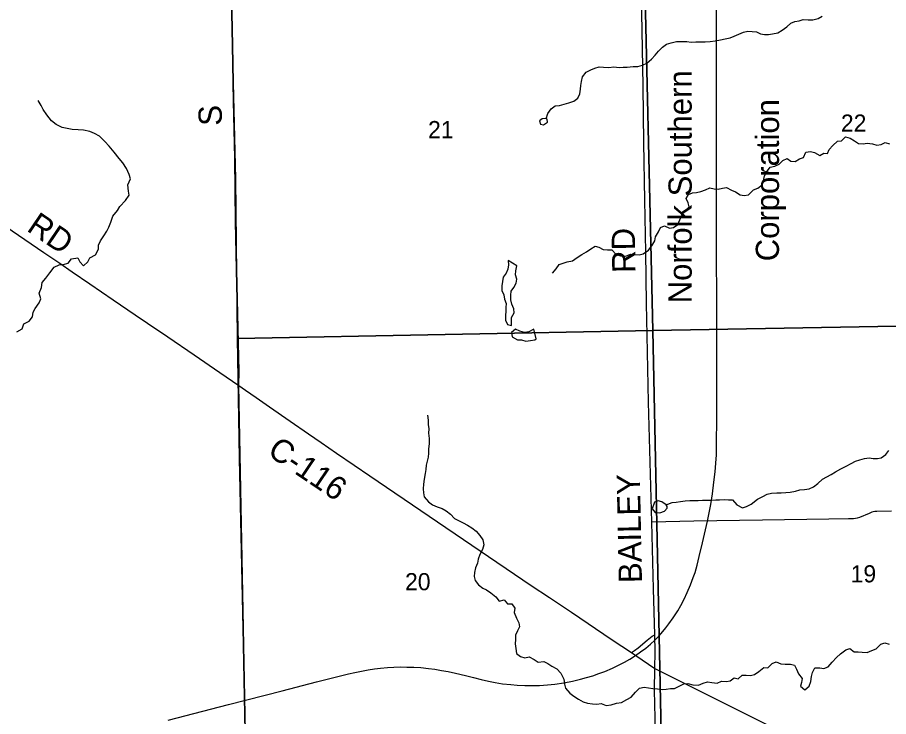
# Model space of a CAD drawing. Extents: x 0 to 34, y 0 to 22.
# Drawn here: x 6.707 to 8.833, y 18.248 to 19.953 of the extents above; entities that cross this region are included whole.
import ezdxf

# ---------------------------------------------------------------- set-up
doc = ezdxf.new("R2010")
doc.units = 0
for name, color, linetype in [('GM_X_Corporation', 7, 'Continuous'), ('GM_X_County_Road', 7, 'Continuous'), ('GM_X_County_Road_Text', 7, 'Continuous'), ('GM_X_Minor_Lake', 7, 'Continuous'), ('GM_X_Minor_River', 7, 'Continuous'), ('GM_X_Rail_Line', 7, 'Continuous'), ('GM_X_Rail_Line_Text', 7, 'Continuous'), ('GM_X_Section_Text', 7, 'Continuous')]:
    doc.layers.add(name, color=color, linetype=linetype)

msp = doc.modelspace()

# ---------------------------------------------------------------- linework, layer by layer
at = {"layer": 'GM_X_Corporation'}
for points in [[(9.7895, 15.1275), (9.7895, 20.2375), (9.7789, 20.2374), (8.9707, 20.221), (8.4324, 20.2139), (8.2231, 20.2112), (7.2254, 20.198), (7.2266, 20.122), (7.2291, 20.0061), (7.2317, 19.8848), (7.2344, 19.7492), (7.237, 19.6097), (7.2392, 19.4543), (7.2426, 19.2998), (7.2468, 19.0896), (7.2467, 19.0557), (7.2751, 17.5764), (7.2764, 17.5202), (7.2799, 17.4174), (7.283, 17.3071), (7.2872, 17.1772)], [(7.2872, 17.1772), (7.283, 17.3071), (7.2799, 17.4174), (7.2764, 17.5202), (7.2751, 17.5764), (7.2467, 19.0557), (7.2468, 19.0896), (7.2426, 19.2998), (7.2392, 19.4543), (7.237, 19.6097), (7.2344, 19.7492), (7.2317, 19.8848), (7.2291, 20.0061), (7.2266, 20.122), (7.2254, 20.198), (6.0786, 20.1754), (5.7004, 20.168), (4.9925, 20.1548), (3.1549, 20.1187), (2.9895, 20.1176), (2.9895, 14.989)]]:
    msp.add_lwpolyline(points, dxfattribs=at)
for points in [[(9.2406, 20.2272), (9.2644, 19.2076), (8.2571, 19.1893), (8.2335, 20.2135), (8.7368, 20.2215)], [(8.2335, 20.2135), (8.2571, 19.1893), (7.2437, 19.1696), (7.2401, 19.5595), (7.2243, 20.1958), (7.7364, 20.2052)], [(8.2571, 19.1893), (9.2644, 19.2076), (9.2853, 18.1891), (8.2786, 18.1687)], [(7.2437, 19.1696), (8.2571, 19.1893), (8.2786, 18.1687), (7.2643, 18.1469), (7.2627, 18.2368), (7.2488, 18.8774)]]:
    msp.add_lwpolyline(points, close=True, dxfattribs=at)
at = {"layer": 'GM_X_County_Road'}
for points in [[(8.2622, 18.3652), (8.2632, 18.4054), (8.2621, 18.4472), (8.2592, 18.5595), (8.2549, 18.7216), (8.2466, 19.0147), (8.2435, 19.1769), (8.2421, 19.255), (8.2402, 19.3805), (8.2379, 19.507), (8.2357, 19.6472), (8.2338, 19.785), (8.2321, 19.8769), (8.2296, 20.0073), (8.2268, 20.1925), (8.2264, 20.1978), (8.2261, 20.2017), (8.2255, 20.2048), (8.2246, 20.2076), (8.2233, 20.2106), (8.2177, 20.2203)], [(7.2469, 19.0552), (7.247, 19.089), (7.2428, 19.2992), (7.2394, 19.4537), (7.2372, 19.6092), (7.2346, 19.7487), (7.2319, 19.8843), (7.2293, 20.0056), (7.2268, 20.1215), (7.2256, 20.1974)], [(6.0866, 19.9058), (6.1443, 19.8572), (6.2021, 19.8083), (6.2352, 19.7801), (6.2988, 19.727), (6.3765, 19.6635), (6.4512, 19.6033), (6.4897, 19.573), (6.5179, 19.5524), (6.5426, 19.5352), (6.5762, 19.5126), (6.6344, 19.4729), (6.6938, 19.4327), (6.7714, 19.3798), (6.8099, 19.3535), (6.8403, 19.3326), (6.8836, 19.3029), (6.9403, 19.2642), (6.994, 19.2279), (7.0243, 19.2074), (7.0735, 19.1741), (7.1379, 19.1298), (7.2009, 19.0868), (7.2469, 19.0552)], [(7.3099, 16.0628), (7.3051, 16.5699), (7.3048, 16.5907), (7.3, 16.7502), (7.2945, 16.9345), (7.2913, 17.051), (7.2874, 17.1766), (7.2832, 17.3066), (7.2801, 17.4169), (7.2766, 17.5196), (7.2753, 17.5759), (7.2469, 19.0552)], [(7.2469, 19.0552), (7.2635, 19.0438), (7.2892, 19.0258), (7.3219, 19.0031), (7.3726, 18.968), (7.4174, 18.9373), (7.4478, 18.9162), (7.4856, 18.8902), (7.5283, 18.8609), (7.5667, 18.8345), (7.9608, 18.5675), (8.0049, 18.538), (8.0589, 18.5019), (8.1586, 18.4345), (8.2051, 18.4038), (8.2313, 18.3857), (8.2622, 18.3652)], [(8.8402, 18.7488), (8.8039, 18.7481), (8.7995, 18.7478), (8.7954, 18.7469), (8.792, 18.746), (8.7884, 18.7447), (8.7852, 18.7433), (8.762, 18.733), (8.7561, 18.7312), (8.752, 18.7304), (8.7473, 18.7301), (8.7435, 18.7299), (8.7394, 18.7298), (8.7348, 18.7299), (8.687, 18.7292), (8.5247, 18.7267), (8.3573, 18.724), (8.2549, 18.7216)], [(8.2051, 18.4038), (8.2125, 18.4089), (8.2217, 18.4153), (8.2434, 18.4338), (8.2556, 18.4437), (8.2621, 18.4472)], [(8.2793, 17.6002), (8.2707, 17.9313), (8.2675, 18.089), (8.2638, 18.2095), (8.2618, 18.3116), (8.2622, 18.3652)], [(8.2622, 18.3652), (8.3616, 18.3152), (8.5946, 18.1992), (8.8266, 18.0841), (8.9262, 18.0351), (9.125, 17.9371), (9.33, 17.8357), (9.4415, 17.781), (9.5684, 17.7185), (9.6907, 17.6578)]]:
    msp.add_lwpolyline(points, dxfattribs=at)
at = {"layer": 'GM_X_Minor_Lake'}
for points in [[(7.9953, 19.7065), (7.9877, 19.7057), (7.9809, 19.7007), (7.9833, 19.6923), (7.9909, 19.6909), (8.0007, 19.6978), (7.9999, 19.705)], [(7.9999, 19.705), (7.9953, 19.7065)], [(7.9041, 19.3603), (7.9053, 19.3493), (7.9035, 19.3386), (7.8998, 19.3291), (7.8919, 19.3191), (7.8905, 19.3089), (7.8887, 19.2986), (7.8892, 19.2872), (7.8938, 19.2762), (7.8954, 19.2659), (7.8997, 19.2553), (7.899, 19.2454), (7.8987, 19.2359), (7.8977, 19.2264), (7.8982, 19.2143), (7.9028, 19.2037), (7.9127, 19.2015), (7.9126, 19.2212), (7.9189, 19.2327), (7.9181, 19.2422), (7.9134, 19.2535), (7.9107, 19.2645), (7.9113, 19.2752), (7.912, 19.2851), (7.918, 19.2946), (7.924, 19.3049), (7.9258, 19.3145), (7.9227, 19.3255), (7.923, 19.3353), (7.9259, 19.3468)], [(7.9259, 19.3468), (7.9041, 19.3603)], [(7.9672, 19.1924), (7.9551, 19.1862), (7.9441, 19.1846), (7.933, 19.1876), (7.9223, 19.1924), (7.9125, 19.1844), (7.9145, 19.1741), (7.9268, 19.1662), (7.9366, 19.1667), (7.9473, 19.1634), (7.9587, 19.1646), (7.9694, 19.1662), (7.9724, 19.1689)], [(7.9724, 19.1689), (7.9672, 19.1924)], [(8.2901, 18.7639), (8.2794, 18.7711), (8.2703, 18.774), (8.2616, 18.7706), (8.2556, 18.7545), (8.2629, 18.7455), (8.2743, 18.7444), (8.2861, 18.7487), (8.2921, 18.756), (8.2925, 18.7598)], [(8.2925, 18.7598), (8.2901, 18.7639)]]:
    msp.add_lwpolyline(points, dxfattribs=at)
at = {"layer": 'GM_X_Minor_River'}
for points in [[(7.9968, 19.706), (8.0013, 19.7187), (8.0096, 19.7302), (8.0194, 19.7371), (8.03, 19.7379), (8.041, 19.7415), (8.0524, 19.7446), (8.0645, 19.7492), (8.0747, 19.7565), (8.0796, 19.7668), (8.0806, 19.7779), (8.0821, 19.7874), (8.0831, 19.7969), (8.0861, 19.8083), (8.0951, 19.8194), (8.1064, 19.8256), (8.1163, 19.8291), (8.1269, 19.8322), (8.1368, 19.8319), (8.1501, 19.8309), (8.1619, 19.8325), (8.1752, 19.8311), (8.1851, 19.8315), (8.1946, 19.832), (8.2091, 19.8333), (8.2209, 19.8337), (8.2319, 19.8369), (8.2432, 19.8415), (8.2545, 19.8511), (8.2632, 19.8611), (8.2711, 19.8706), (8.2813, 19.8802), (8.2911, 19.8879), (8.3025, 19.8914), (8.315, 19.8945), (8.3272, 19.8946), (8.3405, 19.894), (8.3508, 19.8929), (8.3622, 19.8938), (8.374, 19.8935), (8.385, 19.8932), (8.3972, 19.8941), (8.4097, 19.8961), (8.4222, 19.8984), (8.434, 19.9008), (8.4458, 19.9036), (8.456, 19.9071), (8.4674, 19.9121), (8.4787, 19.9168), (8.4894, 19.9199), (8.4996, 19.9184), (8.5107, 19.9178), (8.5202, 19.9129), (8.5297, 19.9118), (8.54, 19.9115), (8.5499, 19.9128), (8.5624, 19.9155), (8.5734, 19.9224), (8.5847, 19.9305), (8.5945, 19.9393), (8.6044, 19.9432), (8.6143, 19.9448), (8.6241, 19.9479), (8.6363, 19.9469), (8.6481, 19.947), (8.6606, 19.9501), (8.6708, 19.9559)], [(6.9308, 19.6387), (6.9202, 19.6506), (6.907, 19.6632), (6.8951, 19.6698), (6.8839, 19.6744), (6.8682, 19.6779), (6.8549, 19.6791), (6.84, 19.6795), (6.8278, 19.6819), (6.816, 19.6846), (6.8017, 19.6915), (6.7897, 19.7011), (6.7783, 19.7153), (6.7697, 19.7288), (6.7645, 19.7386), (6.7577, 19.7502)], [(8.0124, 19.3296), (8.0218, 19.3399), (8.029, 19.3503), (8.0384, 19.3537), (8.0487, 19.3569), (8.0612, 19.3589), (8.0729, 19.3677), (8.0846, 19.3746), (8.0956, 19.3816), (8.1058, 19.3889), (8.1164, 19.3954), (8.1259, 19.3928), (8.1359, 19.3872), (8.1469, 19.3865), (8.1576, 19.3859), (8.1683, 19.3749), (8.1786, 19.3712), (8.1916, 19.3706), (8.2033, 19.3752), (8.214, 19.3745), (8.2239, 19.3739), (8.2337, 19.3762), (8.2466, 19.3851), (8.2552, 19.3958), (8.262, 19.408), (8.2638, 19.4175), (8.2713, 19.4297), (8.2761, 19.4404), (8.286, 19.445), (8.2978, 19.4391), (8.3081, 19.4403), (8.3183, 19.4483), (8.3231, 19.459), (8.328, 19.4708), (8.3347, 19.4808), (8.3464, 19.4911), (8.3433, 19.5006), (8.3386, 19.5112), (8.3443, 19.5208), (8.3545, 19.525), (8.364, 19.5262), (8.3746, 19.5286), (8.3856, 19.5321), (8.3962, 19.5375), (8.4069, 19.5353), (8.4168, 19.5339), (8.4274, 19.5366), (8.4373, 19.5382), (8.4495, 19.5315), (8.4594, 19.5274), (8.4705, 19.5206), (8.4804, 19.5188), (8.4907, 19.52), (8.5031, 19.5323), (8.5134, 19.5362), (8.5239, 19.5446), (8.5273, 19.5545), (8.5302, 19.5663), (8.5347, 19.5759), (8.5437, 19.5874), (8.5551, 19.5905), (8.5661, 19.5948), (8.5748, 19.6043), (8.585, 19.609), (8.5945, 19.6022), (8.6052, 19.6015), (8.615, 19.6084), (8.6249, 19.6116), (8.6305, 19.6242), (8.6426, 19.6258), (8.6522, 19.6239), (8.6648, 19.6161), (8.6746, 19.6218), (8.6841, 19.6212), (8.6875, 19.6311), (8.6969, 19.6406), (8.7078, 19.651), (8.7181, 19.6522), (8.7279, 19.6618), (8.7393, 19.6585), (8.7493, 19.6517), (8.7596, 19.6457), (8.771, 19.645), (8.7805, 19.6463), (8.7938, 19.6448), (8.8045, 19.6415), (8.8144, 19.6431), (8.8246, 19.6481), (8.8353, 19.6444)], [(6.7052, 19.1859), (6.7183, 19.1931), (6.7222, 19.2057), (6.7358, 19.2118), (6.7439, 19.223), (6.7455, 19.2337), (6.7499, 19.2433), (6.7602, 19.2572), (6.7638, 19.2668), (6.76, 19.2804), (6.7654, 19.2942), (6.767, 19.3064), (6.7763, 19.3172), (6.7855, 19.3304), (6.7966, 19.3439), (6.8086, 19.3496), (6.8181, 19.3502), (6.8306, 19.3539), (6.8391, 19.3639), (6.8539, 19.367), (6.8594, 19.3572), (6.8684, 19.3475), (6.8784, 19.3569), (6.8835, 19.3669), (6.8974, 19.3737), (6.9043, 19.3875), (6.9049, 19.3978), (6.9096, 19.4082), (6.918, 19.4202), (6.9254, 19.4313), (6.9301, 19.4413), (6.9344, 19.4536), (6.9393, 19.4685), (6.9512, 19.4817), (6.9567, 19.4918), (6.9704, 19.5065), (6.9796, 19.5193), (6.9779, 19.5295), (6.976, 19.5447), (6.9828, 19.5597), (6.9796, 19.5698), (6.9728, 19.5845), (6.9641, 19.5984), (6.9554, 19.6092), (6.9429, 19.6241), (6.9308, 19.6387)], [(7.7074, 18.9832), (7.709, 18.9706), (7.7091, 18.96), (7.7107, 18.9498), (7.7101, 18.9391), (7.7117, 18.9262), (7.7115, 18.9125), (7.7104, 18.9007), (7.7097, 18.8904), (7.7091, 18.8806), (7.7065, 18.871), (7.7043, 18.8608), (7.7033, 18.8505), (7.7022, 18.8406), (7.6997, 18.8265), (7.6975, 18.8143), (7.6972, 18.8029), (7.6977, 18.7934), (7.6993, 18.7839), (7.7104, 18.7711), (7.72, 18.7643), (7.7311, 18.7595), (7.7433, 18.755), (7.7532, 18.7498), (7.7639, 18.7415), (7.7732, 18.7309), (7.7835, 18.7257), (7.7942, 18.7205), (7.8049, 18.7148), (7.816, 18.7077), (7.8263, 18.6998), (7.8355, 18.6892), (7.8425, 18.6787), (7.8452, 18.6669), (7.8419, 18.6551), (7.8356, 18.6432), (7.8311, 18.6318), (7.8293, 18.6219), (7.8244, 18.6101), (7.8222, 18.5991), (7.8216, 18.5892), (7.8236, 18.5797), (7.8324, 18.5691), (7.8424, 18.5608), (7.8519, 18.5571), (7.8622, 18.5492), (7.8741, 18.5394), (7.8826, 18.5292), (7.8943, 18.5323), (7.9032, 18.5225), (7.9134, 18.5226), (7.9204, 18.5124), (7.919, 18.5014), (7.9244, 18.4874), (7.9302, 18.4764), (7.9322, 18.4665), (7.927, 18.457), (7.9225, 18.4463), (7.9222, 18.4353), (7.9219, 18.4246), (7.9232, 18.414), (7.9248, 18.4015), (7.9344, 18.3939), (7.9454, 18.3906), (7.956, 18.393), (7.9679, 18.387), (7.9778, 18.3802), (7.9911, 18.3815), (8.0011, 18.377), (8.011, 18.3702), (8.0229, 18.3642), (8.0332, 18.3533), (8.0402, 18.3385), (8.0418, 18.3264), (8.0442, 18.3169), (8.0546, 18.3044), (8.0645, 18.2973), (8.076, 18.2898), (8.0871, 18.2838), (8.0978, 18.2804), (8.11, 18.2786), (8.121, 18.2776), (8.1312, 18.2792), (8.1435, 18.2743), (8.1556, 18.276), (8.1685, 18.2799), (8.1807, 18.2822), (8.1939, 18.2888), (8.2049, 18.295), (8.2151, 18.3072), (8.2252, 18.3168), (8.2366, 18.3192), (8.2465, 18.3177), (8.2576, 18.3163), (8.269, 18.3149), (8.28, 18.3138), (8.2899, 18.3143), (8.3002, 18.3159), (8.3104, 18.316), (8.3214, 18.3218), (8.3332, 18.3272)], [(8.2901, 18.7639), (8.3049, 18.7698), (8.3144, 18.7706), (8.3247, 18.7722), (8.3365, 18.7738), (8.3479, 18.7743), (8.3581, 18.7747), (8.368, 18.7748), (8.3787, 18.7757), (8.4, 18.7758), (8.411, 18.7763), (8.4205, 18.776), (8.4323, 18.7769), (8.4422, 18.7762), (8.4521, 18.7759), (8.4624, 18.7642), (8.4762, 18.7567), (8.4857, 18.7602), (8.4978, 18.7656), (8.5133, 18.7783), (8.5258, 18.7848), (8.5364, 18.7899), (8.547, 18.7922), (8.5599, 18.7935), (8.571, 18.7932), (8.5824, 18.7944), (8.593, 18.7952), (8.6055, 18.7972), (8.6165, 18.8004), (8.6276, 18.8012), (8.6386, 18.8028), (8.6496, 18.8079), (8.6601, 18.8159), (8.6714, 18.827), (8.6817, 18.8324), (8.6923, 18.8378), (8.7036, 18.8444), (8.7161, 18.8521), (8.729, 18.8583), (8.7411, 18.8648), (8.7524, 18.871), (8.7627, 18.8741), (8.7741, 18.8769), (8.7855, 18.8785), (8.795, 18.8774), (8.8056, 18.8771), (8.8151, 18.8784), (8.8261, 18.8868), (8.8336, 18.8964)], [(8.3332, 18.3272), (8.3427, 18.328), (8.3553, 18.3247), (8.3693, 18.3244), (8.3807, 18.3287), (8.3906, 18.3326), (8.4016, 18.3308), (8.4145, 18.329), (8.4252, 18.334), (8.437, 18.3329), (8.4464, 18.3345), (8.4563, 18.3422), (8.4658, 18.3392), (8.4756, 18.3488), (8.4855, 18.3489), (8.4958, 18.3475), (8.5056, 18.3502), (8.5162, 18.3579), (8.5283, 18.3675), (8.5378, 18.3668), (8.5484, 18.3768), (8.5586, 18.3807), (8.5701, 18.3758), (8.5803, 18.3751), (8.5933, 18.3756), (8.6028, 18.373), (8.6078, 18.3632), (8.6133, 18.3518), (8.6217, 18.3405), (8.6203, 18.331), (8.6181, 18.3214), (8.6284, 18.3124), (8.6386, 18.3216), (8.6427, 18.3327), (8.6449, 18.3452), (8.6471, 18.3548), (8.6531, 18.3666), (8.6652, 18.3663), (8.6751, 18.3649), (8.685, 18.3691), (8.6948, 18.3802), (8.7053, 18.3913), (8.7155, 18.4009), (8.7284, 18.4101), (8.7382, 18.4133), (8.749, 18.4054), (8.7588, 18.4054), (8.7684, 18.4047), (8.7805, 18.4037), (8.7923, 18.4087), (8.8021, 18.413), (8.8138, 18.4245), (8.8233, 18.4276), (8.834, 18.4239)]]:
    msp.add_lwpolyline(points, dxfattribs=at)
at = {"layer": 'GM_X_Rail_Line'}
msp.add_lwpolyline([(7.0748, 18.2389), (7.2218, 18.2769), (7.3525, 18.3104), (7.4367, 18.332), (7.4921, 18.3458), (7.5146, 18.3518), (7.5306, 18.3554), (7.5469, 18.3587), (7.563, 18.3617), (7.5782, 18.3639), (7.5929, 18.3657), (7.6098, 18.3671), (7.6256, 18.368), (7.6416, 18.3685), (7.6574, 18.3684), (7.6745, 18.368), (7.6915, 18.367), (7.7098, 18.365), (7.7256, 18.363), (7.7416, 18.3602), (7.758, 18.3571), (7.7755, 18.3534), (7.7999, 18.3475), (7.8201, 18.3425), (7.8389, 18.3379), (7.8563, 18.3339), (7.8727, 18.3308), (7.8908, 18.3278), (7.9109, 18.3256), (7.926, 18.3242), (7.9448, 18.3233), (7.9615, 18.3231), (7.9807, 18.3234), (8.0006, 18.325), (8.0182, 18.3267), (8.0405, 18.3298), (8.0617, 18.334), (8.081, 18.3386), (8.0957, 18.3427), (8.1107, 18.3473), (8.1257, 18.3523), (8.1402, 18.3579), (8.1587, 18.3658), (8.1736, 18.3729), (8.1884, 18.3806), (8.2014, 18.3877), (8.2154, 18.3963), (8.2275, 18.4052), (8.2403, 18.4148), (8.2516, 18.4244), (8.2622, 18.434), (8.2718, 18.444), (8.282, 18.4553), (8.2894, 18.4641), (8.2968, 18.4737), (8.3072, 18.4884), (8.3184, 18.5057), (8.3256, 18.5181), (8.3339, 18.5336), (8.3416, 18.5506), (8.3497, 18.5688), (8.3562, 18.5865), (8.3604, 18.5988), (8.3657, 18.6171), (8.3707, 18.6379), (8.3787, 18.6711), (8.391, 18.7245), (8.3989, 18.7648), (8.4029, 18.7913), (8.4067, 18.8192), (8.4093, 18.8443), (8.4111, 18.866), (8.4125, 18.8862), (8.4131, 18.9034), (8.4138, 18.9844), (8.4134, 19.1398), (8.4129, 19.4992), (8.4128, 19.715), (8.4128, 19.8249), (8.4128, 19.913), (8.4124, 20.2199)], dxfattribs=at)

# ---------------------------------------------------------------- texts
at = {"layer": 'GM_X_County_Road_Text'}
for s, height, rotation, p in [('S', 0.0568, 91.2447, (7.2061, 19.6893)), ('RD', 0.05682, 325.7697, (6.727, 19.434)), ('RD', 0.05682, 90.9872, (8.2153, 19.3303)), ('C-116', 0.05682, 325.9294, (7.314, 18.8872)), ('BAILEY', 0.05682, 91.1161, (8.2311, 18.5736))]:
    msp.add_text(s, height=height, rotation=rotation, dxfattribs=at).set_placement(p)
at = {"layer": 'GM_X_Rail_Line_Text'}
for s, p in [('Norfolk Southern', (8.3523, 19.2557)), ('Corporation', (8.5653, 19.3582))]:
    msp.add_text(s, height=0.056629, rotation=90, dxfattribs=at).set_placement(p)
at = {"layer": 'GM_X_Section_Text'}
for s, p in [('22', (8.7164, 19.6744)), ('21', (7.7089, 19.6585)), ('19', (8.7402, 18.5749)), ('20', (7.6527, 18.5557))]:
    msp.add_text(s, height=0.04186, rotation=0, dxfattribs=at).set_placement(p)

doc.saveas('drawing.dxf')
